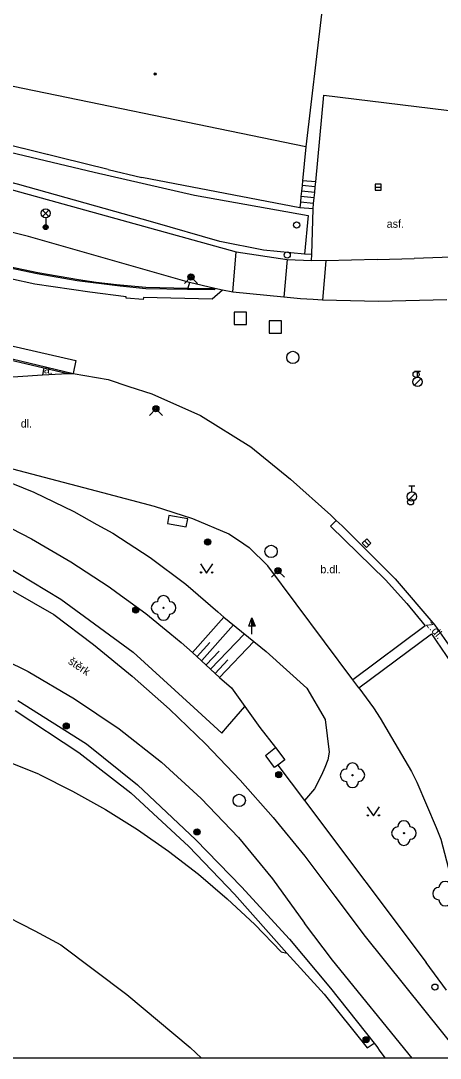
# Model space of a CAD drawing. Extents: x -600309 to -598967, y -1161267 to -1160292.
# Drawn here: x -599761.8 to -599727.7, y -1161267 to -1161182.7 of the extents above; entities that cross this region are included whole.
import ezdxf

# ---------------------------------------------------------------- set-up
doc = ezdxf.new("R2010")
doc.units = 0
for name, color, linetype in [('Level 10', 7, 'Continuous'), ('Level 11', 7, 'Continuous'), ('Level 13', 7, 'Continuous'), ('Level 14', 7, 'Continuous'), ('Level 15', 7, 'Continuous'), ('Level 22', 7, 'Continuous'), ('Level 25', 7, 'Continuous'), ('Level 26', 7, 'Continuous'), ('Level 27', 7, 'Continuous'), ('Level 28', 7, 'Continuous'), ('Level 31', 7, 'Continuous'), ('Level 33', 7, 'Continuous'), ('Level 36', 7, 'Continuous'), ('Level 39', 7, 'Continuous'), ('Level 40', 7, 'Continuous'), ('Level 5', 7, 'Continuous'), ('Level 6', 7, 'Continuous'), ('Level 7', 7, 'Continuous'), ('Level 8', 7, 'Continuous'), ('Vrstva 63', 7, 'Continuous')]:
    doc.layers.add(name, color=color, linetype=linetype)

msp = doc.modelspace()

# ---------------------------------------------------------------- linework, layer by layer
at = {"layer": 'Level 10'}
for points in [[(-599748.1, -1161204), (-599761.2, -1161200.27), (-599773.44, -1161197.2), (-599794.4, -1161191.77), (-599796.23, -1161191.2199), (-599797.26, -1161191.17), (-599803.28, -1161191.38), (-599805.99, -1161190.96)], [(-599746.06, -1161204.5), (-599748.1, -1161204)], [(-599745.42, -1161204.64), (-599746.06, -1161204.5)], [(-599744.6, -1161204.79), (-599745.42, -1161204.64)], [(-599740.44, -1161205.21), (-599744.6, -1161204.79)], [(-599737.3, -1161205.43), (-599738.07, -1161205.39), (-599739.1, -1161205.34), (-599740.44, -1161205.21)], [(-599727.18, -1161205.41), (-599732.75, -1161205.54), (-599737.3, -1161205.43)], [(-599769.62, -1161211.46), (-599768.65, -1161211.6599), (-599767.21, -1161211.84), (-599765.69, -1161211.88), (-599760.07, -1161211.51)], [(-599760.07, -1161211.51), (-599757.99, -1161211.4099)], [(-599757.99, -1161211.4099), (-599757.56, -1161211.39)], [(-599757.56, -1161211.39), (-599754.71, -1161211.9), (-599753.03, -1161212.45), (-599751.18, -1161213.06), (-599747.21, -1161214.81), (-599743.13, -1161217.35), (-599739.89, -1161219.99), (-599736.63, -1161222.9099), (-599736.18, -1161223.34)], [(-599736.18, -1161223.34), (-599735.7, -1161223.78), (-599731.39, -1161228.07), (-599728.17, -1161231.85), (-599726.46, -1161234.28), (-599725.88, -1161235.14)]]:
    msp.add_lwpolyline(points, dxfattribs=at)
at = {"layer": 'Level 11'}
for points in [[(-599817.03, -1161183.79), (-599816.51, -1161181.02), (-599811.69, -1161182.2), (-599811.04, -1161179.46), (-599804.82, -1161181.04), (-599797.7, -1161183), (-599797.4, -1161182.35), (-599791.19, -1161184.45), (-599782.9, -1161187.36), (-599782.6599, -1161186.58), (-599777.51, -1161187.59), (-599768.02, -1161189.2199), (-599768.12, -1161189.86), (-599766.9099, -1161190.05), (-599767.26, -1161192.34), (-599755.87, -1161195.04), (-599747.71, -1161196.9099), (-599738.4699, -1161198.57), (-599738.77, -1161201.71)], [(-599738.77, -1161201.71), (-599742.1, -1161201.38), (-599745.65, -1161200.67), (-599751.09, -1161199.11), (-599762.08, -1161196.03), (-599767.55, -1161194.6), (-599778.5, -1161191.7), (-599783.83, -1161190.3), (-599789.34, -1161188.85), (-599795.02, -1161187.46), (-599797.14, -1161187.2199), (-599799.08, -1161187.1599), (-599800.78, -1161187.23), (-599806.37, -1161186.93), (-599809.4, -1161186.37), (-599812.06, -1161185.59), (-599817.03, -1161183.79)], [(-599737.85, -1161195.84), (-599737.2, -1161188.79)], [(-599737.2, -1161188.79), (-599725.89, -1161190.17)], [(-599745.42, -1161204.64), (-599746.28, -1161205.37), (-599751.85, -1161205.2199), (-599751.87, -1161205.39), (-599753.27, -1161205.29), (-599753.26, -1161205.1599), (-599756.2, -1161204.8), (-599760.68, -1161204.13), (-599764.68, -1161203.28), (-599768.19, -1161202.46), (-599771.96, -1161201.39), (-599781.15, -1161199.04), (-599803.88, -1161192.86), (-599806.8, -1161191.67), (-599806.4699, -1161190.89)], [(-599746.06, -1161204.5), (-599746.07, -1161204.61), (-599748.27, -1161204.57), (-599751.67, -1161204.51), (-599753.75, -1161204.31), (-599757.24, -1161203.86), (-599760.49, -1161203.3), (-599763.33, -1161202.7199), (-599766.68, -1161201.9699), (-599770.31, -1161200.93), (-599780.81, -1161198.14), (-599803.35, -1161192.1), (-599804.74, -1161191.6599), (-599806.4699, -1161190.89)], [(-599803.36, -1161191.94), (-599800.04, -1161192.82), (-599780.76, -1161198.03), (-599771.54, -1161200.49), (-599766.59, -1161201.84), (-599764.9, -1161202.2199), (-599762.78, -1161202.71), (-599760.43, -1161203.2), (-599757.14, -1161203.76), (-599755.7, -1161203.9699), (-599754.04, -1161204.17), (-599751.6599, -1161204.4), (-599748.24, -1161204.48)], [(-599816.82, -1161196.15), (-599816.54, -1161195.04), (-599801.79, -1161199.08), (-599769.68, -1161207.45), (-599763.77, -1161208.87), (-599757.34, -1161210.34), (-599757.56, -1161211.39)], [(-599769.36, -1161194.62), (-599767.74, -1161195.05), (-599744.31, -1161201.51)], [(-599816.82, -1161196.15), (-599802.09, -1161199.99), (-599770.37, -1161208.19), (-599764.69, -1161209.7), (-599757.56, -1161211.39)], [(-599737.89, -1161196.24), (-599738.96, -1161196.14)], [(-599737.85, -1161195.84), (-599738.92, -1161195.74)], [(-599737.89, -1161196.24), (-599737.85, -1161195.84)], [(-599814.67, -1161196.86), (-599770.4, -1161208.31), (-599764.79, -1161209.81), (-599759.96, -1161210.93)], [(-599737.93, -1161196.69), (-599739.01, -1161196.59)], [(-599737.98, -1161197.14), (-599737.93, -1161196.69)], [(-599737.93, -1161196.69), (-599737.89, -1161196.24)], [(-599738.02, -1161197.58), (-599739.09, -1161197.48)], [(-599737.98, -1161197.14), (-599739.05, -1161197.03)], [(-599738.06, -1161198.03), (-599738.02, -1161197.58)], [(-599738.02, -1161197.58), (-599737.98, -1161197.14)], [(-599738.06, -1161198.03), (-599739.13, -1161197.93)], [(-599744.6, -1161204.79), (-599744.31, -1161201.51)], [(-599744.31, -1161201.51), (-599740.18, -1161202.13)], [(-599738.17, -1161201.73), (-599738.77, -1161201.71)], [(-599740.18, -1161202.13), (-599740.44, -1161205.21)], [(-599740.18, -1161202.13), (-599738.18, -1161202.21)], [(-599737.03, -1161202.26), (-599737.3, -1161205.43)], [(-599748.1, -1161204), (-599748.24, -1161204.48)], [(-599748.24, -1161204.48), (-599746.06, -1161204.5)], [(-599759.96, -1161210.93), (-599760.07, -1161211.51)], [(-599759.96, -1161210.93), (-599757.99, -1161211.4099)], [(-599770.99, -1161216.92), (-599755.1758, -1161221.0671), (-599750.9699, -1161222.17), (-599747.86, -1161223.18), (-599744.9099, -1161224.43), (-599744.1338, -1161224.9522), (-599743.26, -1161225.54), (-599741.73, -1161227.03)], [(-599785.23, -1161218.51), (-599782.9099, -1161219.13), (-599780.6, -1161219.8), (-599778.31, -1161220.52), (-599776.03, -1161221.29), (-599773.78, -1161222.11), (-599771.54, -1161222.99), (-599769.32, -1161223.9099), (-599767.12, -1161224.88), (-599764.43, -1161226.21), (-599758.56, -1161229.74), (-599752.69, -1161234.04), (-599747.7531, -1161238.5453), (-599745.48, -1161240.62), (-599745.0152, -1161240.0802), (-599743.62, -1161238.46)], [(-599749.9, -1161223.59), (-599748.37, -1161223.86), (-599748.25, -1161223.2), (-599749.78, -1161222.93), (-599749.9, -1161223.59)], [(-599736.18, -1161223.34), (-599736.64, -1161223.8), (-599732.17, -1161228.17), (-599730.44, -1161230.08), (-599728.95, -1161231.9099)], [(-599734.82, -1161236.29), (-599741.73, -1161227.03)], [(-599728.95, -1161231.9099), (-599734.82, -1161236.29)], [(-599734.35, -1161236.94), (-599728.45, -1161232.55)], [(-599728.45, -1161232.55), (-599728.07, -1161233.11), (-599726.43, -1161235.51)], [(-599734.35, -1161236.94), (-599734.82, -1161236.29)], [(-599760.36, -1161243.95), (-599777.61, -1161237.06)], [(-599734.35, -1161236.94), (-599733.14, -1161238.57), (-599732.62, -1161239.4099), (-599731.7, -1161240.96), (-599730.07, -1161243.74), (-599729.62, -1161244.59), (-599728.07, -1161248.28), (-599727.69, -1161249.23), (-599725.53, -1161257.4099), (-599725.03, -1161257.33), (-599724.55, -1161257.42), (-599724.08, -1161257.69), (-599723.8, -1161258), (-599723.6, -1161258.5), (-599723.57, -1161259.04), (-599724.0163, -1161264.9439), (-599724.11, -1161266.18)], [(-599762.07, -1161237.98), (-599756.49, -1161241.5)], [(-599762.29, -1161238.77), (-599757.11, -1161242.18)], [(-599743.62, -1161238.46), (-599742.39, -1161240.1599), (-599741.13, -1161241.79)], [(-599756.49, -1161241.5), (-599752.34, -1161244.83)], [(-599757.11, -1161242.18), (-599752.89, -1161245.48)], [(-599741.19, -1161243.4), (-599741.8851, -1161242.4889), (-599741.93, -1161242.43), (-599741.13, -1161241.79)], [(-599741.13, -1161241.79), (-599740.36, -1161242.79), (-599740.93, -1161243.21)], [(-599740.93, -1161243.21), (-599741.19, -1161243.4)], [(-599740.93, -1161243.21), (-599738.76, -1161246.1)], [(-599760.36, -1161243.95), (-599757.61, -1161245.32), (-599754.93, -1161246.82), (-599752.33, -1161248.45), (-599749.81, -1161250.2), (-599747.38, -1161252.08), (-599745.04, -1161254.07), (-599742.8, -1161256.17), (-599740.67, -1161258.38)], [(-599752.34, -1161244.83), (-599747.59, -1161249.28)], [(-599752.89, -1161245.48), (-599748.17, -1161249.83)], [(-599738.76, -1161246.1), (-599728.88, -1161259.26)], [(-599748.17, -1161249.83), (-599744.45, -1161253.7)], [(-599747.59, -1161249.28), (-599743.89, -1161253.11)], [(-599774.31, -1161250.88), (-599770.81, -1161252.11), (-599767.37, -1161253.48), (-599763.99, -1161255), (-599760.68, -1161256.67)], [(-599743.89, -1161253.11), (-599739.99, -1161257.36)], [(-599744.45, -1161253.7), (-599740.19, -1161258.49)], [(-599760.68, -1161256.67), (-599758.58, -1161257.82)], [(-599739.99, -1161257.36), (-599736.6599, -1161261.35)], [(-599758.58, -1161257.82), (-599753.2, -1161261.85), (-599748.05, -1161266.17), (-599747.1304, -1161267.0314)], [(-599740.67, -1161258.38), (-599740.19, -1161258.49)], [(-599740.19, -1161258.49), (-599737.1599, -1161261.83)], [(-599727.2199, -1161261.49), (-599728.88, -1161259.26)], [(-599737.1599, -1161261.83), (-599733.6599, -1161266.19)], [(-599736.6599, -1161261.35), (-599733.09, -1161265.8)], [(-599733.6599, -1161266.19), (-599733.09, -1161265.8)], [(-599733.09, -1161265.8), (-599732.8927, -1161266.0766), (-599732.6317, -1161266.4427), (-599732.2117, -1161267.0314)]]:
    msp.add_lwpolyline(points, dxfattribs=at)
at = {"layer": 'Level 13'}
for p, q in [((-599733.82, -1161257.15), (-599725.8784, -1161267.0314)), ((-599729.9999, -1161267.0314), (-599736.49, -1161259.05))]:
    msp.add_line(p, q, dxfattribs=at)
for points in [[(-599767.61, -1161226.13), (-599759.15, -1161230.9699)], [(-599759.15, -1161230.9699), (-599755.9099, -1161233.4099), (-599752.76, -1161235.98), (-599749.73, -1161238.68), (-599746.8, -1161241.5), (-599743.99, -1161244.43), (-599741.3, -1161247.4699), (-599738.74, -1161250.62), (-599736.3, -1161253.87)], [(-599765.1599, -1161233.69), (-599761.23, -1161235.62), (-599757.45, -1161237.82), (-599753.83, -1161240.27), (-599750.4, -1161242.98), (-599747.1599, -1161245.93), (-599744.14, -1161249.09), (-599741.35, -1161252.46), (-599738.77, -1161256.06)], [(-599736.3, -1161253.87), (-599733.82, -1161257.15)], [(-599736.49, -1161259.05), (-599738.77, -1161256.06)]]:
    msp.add_lwpolyline(points, dxfattribs=at)
at = {"layer": 'Level 14'}
for points in [[(-599764.12, -1161219.7), (-599760.76, -1161221.05), (-599757.5, -1161222.61), (-599755.6301, -1161223.6608), (-599754.35, -1161224.38), (-599751.31, -1161226.35), (-599748.42, -1161228.52), (-599745.8017, -1161230.7767), (-599745.31, -1161231.2), (-599741.89, -1161233.98), (-599738.57, -1161236.9699)], [(-599769.29, -1161221.12), (-599764.24, -1161223.15), (-599760.95, -1161224.84), (-599757.75, -1161226.7), (-599754.65, -1161228.73), (-599754.0211, -1161229.1885), (-599751.6599, -1161230.9099), (-599749.718, -1161232.4933), (-599748.79, -1161233.25), (-599747.87, -1161234.06), (-599745.67, -1161236.1), (-599744.69, -1161236.95), (-599743.62, -1161238.46)], [(-599738.57, -1161236.9699), (-599737.08, -1161239.52), (-599736.75, -1161242.1599), (-599736.86, -1161242.79), (-599737.11, -1161243.4099), (-599737.37, -1161244.02), (-599737.96, -1161245.14), (-599738.76, -1161246.1)]]:
    msp.add_lwpolyline(points, dxfattribs=at)
at = {"layer": 'Level 15'}
for points in [[(-599747.87, -1161234.06), (-599745.31, -1161231.2)], [(-599747.12, -1161234.73), (-599744.53, -1161231.83)], [(-599746.39, -1161235.4099), (-599743.65, -1161232.55)], [(-599745.67, -1161236.1), (-599742.88, -1161233.18)], [(-599747.5, -1161234.4), (-599746.4699, -1161233.25)], [(-599746.75, -1161235.07), (-599745.7, -1161233.9699)], [(-599746.03, -1161235.76), (-599744.99, -1161234.67)]]:
    msp.add_lwpolyline(points, dxfattribs=at)
at = {"layer": 'Level 22'}
for centre in [(-599750.2199, -1161230.44), (-599734.86, -1161244.04), (-599730.68, -1161248.74)]:
    msp.add_circle(centre, 0.05, dxfattribs=at)
for centre, start, end in [((-599750.2199, -1161229.94), 0, 180), ((-599750.7199, -1161230.44), 90, 270), ((-599749.7199, -1161230.44), 270, 90), ((-599750.2199, -1161230.94), 180, 0), ((-599734.86, -1161243.54), 0, 180), ((-599735.36, -1161244.04), 90, 270), ((-599734.36, -1161244.04), 270, 90), ((-599734.86, -1161244.54), 180, 0), ((-599731.18, -1161248.74), 90, 270), ((-599730.68, -1161248.24), 0, 180), ((-599730.18, -1161248.74), 270, 90), ((-599730.68, -1161249.24), 180, 0), ((-599727.83, -1161253.6599), 90, 270), ((-599727.33, -1161253.1599), 0, 180), ((-599727.33, -1161254.1599), 180, 0)]:
    msp.add_arc(centre, 0.5, start, end, dxfattribs=at)
at = {"layer": 'Level 25'}
for p, q in [((-599743.282, -1161231.928), (-599743.03, -1161231.254)), ((-599743.03, -1161231.928), (-599743.282, -1161231.928)), ((-599743.03, -1161232.58), (-599743.03, -1161231.93))]:
    msp.add_line(p, q, dxfattribs=at)
for points in [[(-599742.78, -1161231.93), (-599743.03, -1161231.93), (-599743.03, -1161231.254), (-599743.03, -1161231.254)], [(-599742.837, -1161231.89), (-599742.99, -1161231.89), (-599742.99, -1161231.477)], [(-599742.895, -1161231.85), (-599742.95, -1161231.85), (-599742.95, -1161231.701)]]:
    msp.add_lwpolyline(points, close=True, dxfattribs=at)
for centre, radius in [((-599746.63, -1161225.09), 0.25), ((-599746.63, -1161225.09), 0.2), ((-599746.63, -1161225.09), 0.15), ((-599746.63, -1161225.09), 0.1), ((-599746.63, -1161225.09), 0.05), ((-599752.48, -1161230.61), 0.25), ((-599752.48, -1161230.61), 0.2), ((-599752.48, -1161230.61), 0.15), ((-599752.48, -1161230.61), 0.1), ((-599752.48, -1161230.61), 0.05), ((-599758.13, -1161240.03), 0.25), ((-599758.13, -1161240.03), 0.2), ((-599758.13, -1161240.03), 0.15), ((-599758.13, -1161240.03), 0.1), ((-599758.13, -1161240.03), 0.05), ((-599740.85, -1161243.99), 0.25), ((-599740.85, -1161243.99), 0.2), ((-599740.85, -1161243.99), 0.15), ((-599740.85, -1161243.99), 0.1), ((-599740.85, -1161243.99), 0.05), ((-599747.5, -1161248.64), 0.25), ((-599747.5, -1161248.64), 0.2), ((-599747.5, -1161248.64), 0.15), ((-599747.5, -1161248.64), 0.1), ((-599747.5, -1161248.64), 0.05), ((-599733.75, -1161265.53), 0.25), ((-599733.75, -1161265.53), 0.2), ((-599733.75, -1161265.53), 0.15), ((-599733.75, -1161265.53), 0.1), ((-599733.75, -1161265.53), 0.05)]:
    msp.add_circle(centre, radius, dxfattribs=at)
at = {"layer": 'Level 26'}
for points in [[(-599744.48, -1161207.4099), (-599743.48, -1161207.4099), (-599743.48, -1161206.4099), (-599744.48, -1161206.4099)], [(-599741.64, -1161208.12), (-599740.64, -1161208.12), (-599740.64, -1161207.12), (-599741.64, -1161207.12)]]:
    msp.add_lwpolyline(points, close=True, dxfattribs=at)
at = {"layer": 'Level 27'}
for p, q in [((-599733.03, -1161196.27), (-599732.53, -1161196.27)), ((-599733.884, -1161225.0005), (-599733.536, -1161225.3595))]:
    msp.add_line(p, q, dxfattribs=at)
for points in [[(-599733.03, -1161196.52), (-599732.53, -1161196.52), (-599732.53, -1161196.02), (-599733.03, -1161196.02)], [(-599734.0635, -1161225.1746), (-599733.7154, -1161225.5335), (-599733.3565, -1161225.1854), (-599733.7046, -1161224.8265)]]:
    msp.add_lwpolyline(points, close=True, dxfattribs=at)
for centre in [(-599739.71, -1161210.1), (-599741.48, -1161225.85), (-599744.07, -1161246.09)]:
    msp.add_circle(centre, 0.5, dxfattribs=at)
at = {"layer": 'Level 28'}
for p, q in [((-599729.82, -1161211.205), (-599729.32, -1161211.205)), ((-599729.57, -1161211.705), (-599729.57, -1161211.205)), ((-599729.828, -1161212.352), (-599729.298, -1161211.822)), ((-599730.28, -1161220.525), (-599729.78, -1161220.525)), ((-599730.03, -1161221.025), (-599730.03, -1161220.525)), ((-599730.288, -1161221.672), (-599729.758, -1161221.142))]:
    msp.add_line(p, q, dxfattribs=at)
for centre, radius in [((-599739.4, -1161199.34), 0.25), ((-599740.17, -1161201.77), 0.25), ((-599729.69, -1161211.48), 0.25), ((-599729.57, -1161212.08), 0.375), ((-599730.03, -1161221.4), 0.375), ((-599730.14, -1161221.83), 0.25), ((-599728.1599, -1161261.25), 0.25)]:
    msp.add_circle(centre, radius, dxfattribs=at)
at = {"layer": 'Level 31'}
for points in [[(-599748.52, -1161204.09), (-599747.99, -1161203.56), (-599747.46, -1161204.09)], [(-599751.37, -1161214.8), (-599750.84, -1161214.27), (-599750.31, -1161214.8)], [(-599741.45, -1161227.96), (-599740.92, -1161227.43), (-599740.39, -1161227.96)]]:
    msp.add_lwpolyline(points, dxfattribs=at)
for centre, radius in [((-599747.99, -1161203.56), 0.25), ((-599747.99, -1161203.56), 0.18), ((-599747.99, -1161203.56), 0.11), ((-599750.84, -1161214.27), 0.25), ((-599750.84, -1161214.27), 0.18), ((-599750.84, -1161214.27), 0.11), ((-599740.92, -1161227.43), 0.25), ((-599740.92, -1161227.43), 0.18), ((-599740.92, -1161227.43), 0.11)]:
    msp.add_circle(centre, radius, dxfattribs=at)
at = {"layer": 'Level 33'}
for p, q in [((-599760.065, -1161198.65), (-599759.535, -1161198.12)), ((-599760.065, -1161198.12), (-599759.535, -1161198.65)), ((-599759.8, -1161198.76), (-599759.8, -1161199.51))]:
    msp.add_line(p, q, dxfattribs=at)
for centre, radius in [((-599759.8, -1161198.385), 0.375), ((-599759.8, -1161199.51), 0.2), ((-599759.8, -1161199.51), 0.1445), ((-599759.8, -1161199.51), 0.0876)]:
    msp.add_circle(centre, radius, dxfattribs=at)
at = {"layer": 'Level 36'}
for points in [[(-599747.2199, -1161226.86), (-599746.7199, -1161227.61), (-599746.2199, -1161226.86)], [(-599733.6599, -1161246.6), (-599733.1599, -1161247.35), (-599732.6599, -1161246.6)]]:
    msp.add_lwpolyline(points, dxfattribs=at)
for centre in [(-599747.1701, -1161227.5598), (-599746.2707, -1161227.5598), (-599733.6101, -1161247.2998), (-599732.7107, -1161247.2998)]:
    msp.add_circle(centre, 0.05, dxfattribs=at)
at = {"layer": 'Level 39'}
for radius in [0.09, 0.0398]:
    msp.add_circle((-599750.9, -1161187.07), radius, dxfattribs=at)
at = {"layer": 'Level 5'}
for points in [[(-599737.38, -1161182.2199), (-599738.65, -1161192.99)], [(-599738.65, -1161192.99), (-599766.02, -1161187.34)]]:
    msp.add_lwpolyline(points, dxfattribs=at)
at = {"layer": 'Level 6'}
msp.add_lwpolyline([(-599732.86, -1161202.14), (-599729.85, -1161202.05)], dxfattribs=at)
at = {"layer": 'Level 7'}
for points in [[(-599754.71, -1161194.82), (-599766.63, -1161191.9), (-599766.5, -1161189.01)], [(-599738.65, -1161192.99), (-599738.92, -1161195.74)], [(-599739.13, -1161197.93), (-599751.99, -1161195.49)], [(-599738.96, -1161196.14), (-599739.01, -1161196.59)], [(-599738.92, -1161195.74), (-599738.96, -1161196.14)], [(-599739.01, -1161196.59), (-599739.05, -1161197.03)], [(-599739.09, -1161197.48), (-599739.13, -1161197.93)], [(-599739.05, -1161197.03), (-599739.09, -1161197.48)], [(-599738.17, -1161201.73), (-599738.06, -1161198.03)], [(-599738.18, -1161202.21), (-599738.17, -1161201.73)], [(-599724.5, -1161201.88), (-599729.85, -1161202.05)], [(-599737.03, -1161202.26), (-599738.18, -1161202.21)], [(-599732.86, -1161202.14), (-599737.03, -1161202.26)]]:
    msp.add_lwpolyline(points, dxfattribs=at)
at = {"layer": 'Level 8'}
msp.add_lwpolyline([(-599754.71, -1161194.82), (-599751.99, -1161195.49)], dxfattribs=at)
at = {"layer": 'Vrstva 63'}
msp.add_lwpolyline([(-600308.541, -1160292.3474), (-598967.1085, -1160292.3474), (-598967.1085, -1161267.0314), (-600308.541, -1161267.0314)], close=True, dxfattribs=at)

# ---------------------------------------------------------------- texts
at = {"layer": 'Level 40'}
for s, p in [('asf.', (-599732.08, -1161199.56)), ('dl.', (-599761.83, -1161215.79)), ('b.dl.', (-599737.4699, -1161227.63))]:
    msp.add_text(s, height=0.65, dxfattribs=at).set_placement(p)
for s, rotation, p in [('a.', 352.02, (-599759.9699, -1161211.36)), ('z.dl.', 310.52, (-599728.92, -1161231.83)), ('štěrk', 326.09, (-599758.03, -1161234.93))]:
    msp.add_text(s, height=0.65, rotation=rotation, dxfattribs=at).set_placement(p)

doc.saveas('drawing.dxf')
